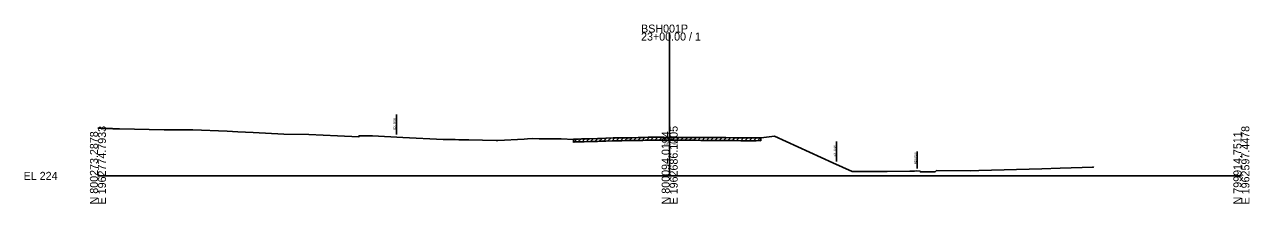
# Model space of a CAD drawing. Extents: x -26 to 1403, y -10 to 19587.
# Drawn here: x -25.7 to 402.8, y 6990.3 to 7053 of the extents above; entities that cross this region are included whole.
import ezdxf

# ---------------------------------------------------------------- set-up
doc = ezdxf.new("R2010")
doc.units = 0
for name, color, linetype in [('Default', 7, 'Continuous'), ('RD_GPK_XS_Cell', 7, 'Continuous'), ('RD_XS_ExGround', 7, 'Continuous'), ('RD_XS_ExPaveRet', 7, 'Continuous'), ('RD_XS_ExRW', 7, 'Continuous'), ('RD_XS_NewRW', 7, 'Continuous'), ('RD_XS_TX_Elev_EX', 7, 'Continuous')]:
    doc.layers.add(name, color=color, linetype=linetype)

msp = doc.modelspace()

# ---------------------------------------------------------------- linework, layer by layer
at = {"layer": 'RD_GPK_XS_Cell'}
for p, q in [((200, 7000), (200, 7050.18)), ((0, 7000), (200, 7000)), ((200, 7000), (400, 7000))]:
    msp.add_line(p, q, dxfattribs=at)
at = {"layer": 'RD_XS_ExGround'}
msp.add_lwpolyline([(0, 7016.73), (1.15, 7016.63), (4.99, 7016.53), (5.31, 7016.51), (7.49, 7016.45), (23.12, 7016.09), (24.1, 7016.08), (25.06, 7016.08), (25.82, 7016.1), (30.01, 7016.13), (33.22, 7016.06), (45.2, 7015.65), (48.9, 7015.45), (54.27, 7015.2), (65, 7014.64), (73.74, 7014.44), (83.84, 7014.01), (91.23, 7013.62), (91.35, 7014.06), (91.86, 7014.07), (93.74, 7014.05), (95.65, 7014.03), (96.09, 7014.03), (106.7, 7013.41), (120.81, 7012.77), (123.99, 7012.74), (124.98, 7012.69), (126.2, 7012.67), (129.7, 7012.61), (139.25, 7012.39), (139.92, 7012.38), (149.12, 7012.88), (150.22, 7012.95), (152.13, 7013.03), (154.39, 7013.02), (156.33, 7012.99), (161.24, 7013), (162.04, 7012.95), (166.34, 7012.73), (166.44, 7012.9), (167, 7012.88), (167.4, 7012.87), (168.06, 7012.88), (169.12, 7012.91), (170.09, 7012.94), (172.06, 7012.98), (174.7, 7013.07), (175.67, 7013.11), (177.68, 7013.19), (180.26, 7013.28), (181.22, 7013.31), (183.28, 7013.32), (184.98, 7013.34), (185.81, 7013.35), (186.85, 7013.36), (188.95, 7013.39), (190.58, 7013.43), (191.39, 7013.46), (192.5, 7013.5), (193.12, 7013.53), (197.48, 7013.53), (197.92, 7013.5), (199.42, 7013.48), (200.27, 7013.48), (201.82, 7013.47), (202.59, 7013.47), (204.9, 7013.46), (205.36, 7013.45), (205.71, 7013.45), (207.18, 7013.46), (207.52, 7013.46), (208.18, 7013.46), (209.29, 7013.45), (210.95, 7013.42), (211.52, 7013.42), (213, 7013.41), (213.74, 7013.4), (214.88, 7013.39), (216.55, 7013.39), (217.16, 7013.39), (219.28, 7013.39), (219.65, 7013.38), (222.09, 7013.34), (222.78, 7013.33), (224.86, 7013.31), (226.03, 7013.31), (227.67, 7013.31), (228.4, 7013.31), (230.28, 7013.32), (231.15, 7013.33), (232.02, 7013.28), (236.69, 7013.89), (257.11, 7004.61), (263.86, 7001.48), (275.66, 7001.57), (276.07, 7001.57), (283.96, 7001.65), (285.7, 7001.69), (286.2, 7001.74), (287.61, 7001.64), (287.72, 7001.39), (292.92, 7001.46), (293.39, 7001.91), (305.39, 7001.8), (308.2, 7001.87), (330.2, 7002.44), (336.62, 7002.74), (348.17, 7003.01), (348.28, 7003.26)], dxfattribs=at)
at = {"layer": 'RD_XS_ExPaveRet'}
for p, q in [((166.34, 7011.73), (167.48, 7012.87)), ((166.34, 7011.73), (166.34, 7012.73)), ((166.34, 7011.73), (166.44, 7011.9)), ((166.44, 7011.9), (167, 7011.88)), ((167, 7011.88), (167.4, 7011.87)), ((167.4, 7011.87), (168.06, 7011.88)), ((167.84, 7011.88), (168.87, 7012.9)), ((168.06, 7011.88), (169.12, 7011.91)), ((169.12, 7011.91), (170.09, 7011.94)), ((169.34, 7011.92), (170.37, 7012.95)), ((170.09, 7011.94), (172.06, 7011.98)), ((170.84, 7011.96), (171.86, 7012.98)), ((172.06, 7011.98), (174.7, 7012.07)), ((172.34, 7011.99), (173.37, 7013.03)), ((173.84, 7012.04), (174.87, 7013.08)), ((174.7, 7012.07), (175.67, 7012.11)), ((175.34, 7012.1), (176.38, 7013.14)), ((175.67, 7012.11), (177.68, 7012.19)), ((176.84, 7012.15), (177.88, 7013.19)), ((177.68, 7012.19), (180.26, 7012.28)), ((178.34, 7012.21), (179.38, 7013.25)), ((179.84, 7012.27), (180.87, 7013.3)), ((180.26, 7012.28), (181.22, 7012.31)), ((181.22, 7012.31), (183.28, 7012.32)), ((181.34, 7012.31), (182.35, 7013.31)), ((182.84, 7012.32), (183.85, 7013.33)), ((183.28, 7012.32), (184.98, 7012.34)), ((184.34, 7012.33), (185.35, 7013.34)), ((184.98, 7012.34), (185.81, 7012.35)), ((185.81, 7012.35), (186.85, 7012.36)), ((185.84, 7012.35), (186.85, 7013.36)), ((186.85, 7012.36), (188.95, 7012.39)), ((187.34, 7012.37), (188.35, 7013.38)), ((188.84, 7012.39), (189.86, 7013.41)), ((188.95, 7012.39), (190.58, 7012.43)), ((190.34, 7012.43), (191.37, 7013.46)), ((190.58, 7012.43), (191.39, 7012.46)), ((191.39, 7012.46), (192.5, 7012.5)), ((191.84, 7012.47), (192.89, 7013.52)), ((192.5, 7012.5), (193.12, 7012.53)), ((193.12, 7012.53), (197.48, 7012.53)), ((193.34, 7012.53), (194.34, 7013.53)), ((194.84, 7012.53), (195.84, 7013.53)), ((196.34, 7012.53), (197.34, 7013.53)), ((197.48, 7012.53), (197.92, 7012.5)), ((197.84, 7012.51), (198.82, 7013.49)), ((197.92, 7012.5), (199.42, 7012.48)), ((199.34, 7012.49), (200.33, 7013.48)), ((199.42, 7012.48), (200.27, 7012.48)), ((200.27, 7012.48), (201.82, 7012.47)), ((200.84, 7012.48), (201.83, 7013.47)), ((201.82, 7012.47), (202.59, 7012.47)), ((202.34, 7012.47), (203.33, 7013.46)), ((202.59, 7012.47), (204.9, 7012.46)), ((203.84, 7012.46), (204.83, 7013.46)), ((204.9, 7012.46), (205.36, 7012.45)), ((205.34, 7012.45), (206.34, 7013.46)), ((205.36, 7012.45), (205.71, 7012.45)), ((205.71, 7012.45), (207.18, 7012.46)), ((206.84, 7012.46), (207.84, 7013.46)), ((207.18, 7012.46), (207.52, 7012.46)), ((207.52, 7012.46), (208.18, 7012.46)), ((208.18, 7012.46), (209.29, 7012.45)), ((208.34, 7012.46), (209.33, 7013.45)), ((209.29, 7012.45), (210.95, 7012.42)), ((209.84, 7012.44), (210.82, 7013.42)), ((210.95, 7012.42), (211.52, 7012.42)), ((211.34, 7012.42), (212.33, 7013.41)), ((211.52, 7012.42), (213, 7012.41)), ((212.84, 7012.41), (213.83, 7013.4)), ((213, 7012.41), (213.74, 7012.4)), ((213.74, 7012.4), (214.88, 7012.39)), ((214.34, 7012.4), (215.33, 7013.39)), ((214.88, 7012.39), (216.55, 7012.39)), ((215.84, 7012.39), (216.84, 7013.39)), ((216.55, 7012.39), (217.16, 7012.39)), ((217.16, 7012.39), (219.28, 7012.39)), ((217.34, 7012.39), (218.34, 7013.39)), ((218.84, 7012.39), (219.83, 7013.38)), ((219.28, 7012.39), (219.65, 7012.38)), ((219.65, 7012.38), (222.09, 7012.34)), ((220.34, 7012.37), (221.32, 7013.35)), ((221.84, 7012.34), (222.83, 7013.33)), ((222.09, 7012.34), (222.78, 7012.33)), ((222.78, 7012.33), (224.86, 7012.31)), ((223.34, 7012.33), (224.33, 7013.32)), ((224.84, 7012.31), (225.84, 7013.31)), ((224.86, 7012.31), (226.03, 7012.31)), ((226.03, 7012.31), (227.67, 7012.31)), ((226.34, 7012.31), (227.34, 7013.31)), ((227.67, 7012.31), (228.4, 7012.31)), ((227.84, 7012.31), (228.84, 7013.31)), ((228.4, 7012.31), (230.28, 7012.32)), ((229.34, 7012.32), (230.34, 7013.32)), ((230.28, 7012.32), (231.15, 7012.33)), ((230.84, 7012.33), (231.8, 7013.29)), ((231.15, 7012.33), (231.84, 7012.29)), ((231.84, 7013.29), (231.84, 7012.29))]:
    msp.add_line(p, q, dxfattribs=at)
at = {"layer": 'RD_XS_ExRW'}
for p, q in [((104.49, 7014.54), (104.49, 7021.54)), ((258.33, 7005.04), (258.33, 7012.04))]:
    msp.add_line(p, q, dxfattribs=at)
at = {"layer": 'RD_XS_NewRW'}
msp.add_line((286.53, 7008.56), (286.53, 7002.56), dxfattribs=at)

# ---------------------------------------------------------------- texts
at = {"layer": 'Default'}
msp.add_text('-', height=0.0001, dxfattribs=at).set_placement((0, 7000))
at = {"layer": 'RD_GPK_XS_Cell'}
for s, p in [('23+00.00 / 1', (190, 7047.38)), ('BSH001P', (190, 7050.18)), ('EL 224', (-26, 6998.6))]:
    msp.add_text(s, height=2.8, dxfattribs=at).set_placement(p)
for s, p in [('N 800273.2878', (0, 6990)), ('E 1962774.7933', (2.8, 6990)), ('N 800094.0194', (200, 6990)), ('E 1962686.1205', (202.8, 6990)), ('N 799914.7511', (400, 6990)), ('E 1962597.4478', (402.8, 6990))]:
    msp.add_text(s, height=2.8, rotation=90, dxfattribs=at).set_placement(p)
at = {"layer": 'RD_XS_ExRW'}
for p in [(104.14, 7016.22), (258.08, 7006.71)]:
    msp.add_text('EX. R/W ', height=0.75, rotation=90, dxfattribs=at).set_placement(p)
at = {"layer": 'RD_XS_NewRW'}
msp.add_text('NEW R/W ', height=0.65, rotation=90, dxfattribs=at).set_placement((286.26, 7004.11))
at = {"layer": 'RD_XS_TX_Elev_EX'}
msp.add_text('237.48', height=1, dxfattribs=at).set_placement((197.95, 7010.98))

doc.saveas('drawing.dxf')
